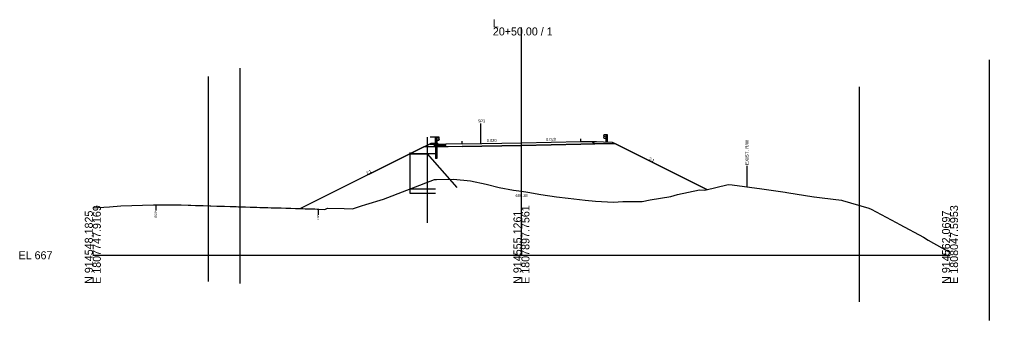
# Model space of a CAD drawing. Extents: x -26 to 1352, y -510 to 9596.
# Drawn here: x -25.7 to 313.8, y 6477.2 to 6582.4 of the extents above; entities that cross this region are included whole.
import ezdxf

# ---------------------------------------------------------------- set-up
doc = ezdxf.new("R2010")
doc.units = 0
for name, color, linetype in [('Exist Cross Section Cell', 7, 'Continuous'), ('Exist XS Center Line Elevation Label', 7, 'Continuous'), ('Exist XS Ground Line', 7, 'Continuous'), ('Old_Level_10', 7, 'Continuous'), ('Prop XS Earthwork Shape', 7, 'Continuous'), ('Prop XS EOT Tick Mark', 7, 'Continuous'), ('Prop XS Exc Vertical Line 1', 7, 'Continuous'), ('Prop XS Exc Vertical Line 2', 7, 'Continuous'), ('Prop XS Exc Vertical Line 3', 7, 'Continuous'), ('Prop XS Exc Vertical Line 4', 7, 'Continuous'), ('Prop XS Finish Grade', 7, 'Continuous'), ('Prop XS Finish Grade Earthwork', 7, 'Continuous'), ('Prop XS Finish Grade Paved Shoulder', 7, 'Continuous'), ('Prop XS Finish Grade Pavement', 7, 'Continuous'), ('Prop XS Guardrail', 7, 'Continuous'), ('Prop XS Hydro Fill Slope Data', 7, 'Continuous'), ('Prop XS Pvmt Edge Slope', 7, 'Continuous'), ('Prop XS SE Text', 7, 'Continuous'), ('Prop XS Shoulder Borrow Shape', 7, 'Continuous'), ('Prop XS Side Slope Text', 7, 'Continuous'), ('Prop XS Subgrade Earthwork', 7, 'Continuous'), ('Typical Curb CELL', 7, 'Continuous')]:
    doc.layers.add(name, color=color, linetype=linetype)

msp = doc.modelspace()

# ---------------------------------------------------------------- linework, layer by layer
at = {"layer": 'Exist Cross Section Cell'}
for p, q in [((150, 6500), (150, 6579.64)), ((0, 6500), (150, 6500)), ((150, 6500), (300, 6500))]:
    msp.add_line(p, q, dxfattribs=at)
at = {"layer": 'Exist XS Ground Line'}
msp.add_lwpolyline([(0, 6516.57), (5.8, 6516.94), (9.82, 6517.24), (21.25, 6517.63), (22.08, 6517.65), (22.94, 6517.64), (25.56, 6517.64), (25.95, 6517.65), (26.05, 6517.65), (28.2, 6517.67), (28.25, 6517.67), (30.74, 6517.59), (30.92, 6517.58), (33.39, 6517.51), (33.43, 6517.51), (33.47, 6517.51), (34.35, 6517.49), (35.89, 6517.44), (35.95, 6517.44), (36.03, 6517.44), (38.44, 6517.37), (38.66, 6517.37), (40.96, 6517.29), (41.3, 6517.28), (43.45, 6517.22), (44.36, 6517.18), (44.91, 6517.16), (45.62, 6517.14), (46.13, 6517.13), (48.12, 6517.06), (48.44, 6517.06), (50.22, 6517.01), (50.94, 6516.98), (51.75, 6516.96), (53.46, 6516.91), (55.01, 6516.86), (55.99, 6516.83), (57.41, 6516.78), (58.47, 6516.75), (59.36, 6516.72), (60.31, 6516.69), (60.65, 6516.68), (61.3, 6516.66), (62.36, 6516.63), (63.46, 6516.61), (64.57, 6516.58), (65.94, 6516.54), (67.51, 6516.5), (68.47, 6516.47), (69.34, 6516.44), (70.99, 6516.39), (72.76, 6516.34), (73.5, 6516.32), (75.41, 6516.26), (75.96, 6516.24), (76.14, 6516.24), (77.7, 6516.19), (78.53, 6516.17), (78.81, 6516.16), (79.12, 6516.15), (81.14, 6516.05), (81.41, 6516.17), (82.12, 6516.48), (87.91, 6516.35), (90.83, 6516.27), (94.06, 6517.29), (95.6, 6517.75), (101.72, 6519.63), (119.57, 6526.48), (120.33, 6526.51), (126.24, 6526.55), (132.22, 6526.01), (137.68, 6524.89), (142.24, 6523.74), (147.24, 6522.81), (150, 6522.38), (152.25, 6522.03), (156.81, 6521.29), (162.26, 6520.39), (166.38, 6519.91), (172.27, 6519.25), (175.94, 6518.93), (182.28, 6518.61), (185.51, 6518.76), (192.29, 6518.82), (195.08, 6519.34), (202.3, 6520.49), (204.65, 6521.21), (212.31, 6522.9), (214.21, 6522.8), (222.32, 6524.77), (223.78, 6524.58), (232.33, 6523.42), (233.35, 6523.29), (242.34, 6522.09), (242.92, 6521.99), (252.35, 6520.48), (252.48, 6520.46), (255.29, 6520.1), (262.05, 6519.25), (262.36, 6519.18), (271.62, 6516.41), (272.38, 6516.15), (281.19, 6511.51), (282.39, 6510.78), (290.75, 6506.28), (292.4, 6505.31), (300, 6500.91)], dxfattribs=at)
at = {"layer": 'Old_Level_10'}
for p, q in [((135.84, 6539.04), (135.84, 6546.09)), ((228.9, 6531.29), (228.9, 6523.89)), ((22.08, 6517.65), (22.08, 6515.6)), ((78.81, 6516.16), (78.81, 6514.11))]:
    msp.add_line(p, q, dxfattribs=at)
at = {"layer": 'Prop XS Earthwork Shape'}
msp.add_lwpolyline([(75.41, 6516.26), (75.96, 6516.24), (76.14, 6516.24), (77.7, 6516.19), (78.53, 6516.17), (78.81, 6516.16), (79.12, 6516.15), (81.14, 6516.05), (81.41, 6516.17), (82.12, 6516.48), (87.91, 6516.35), (90.83, 6516.27), (94.06, 6517.29), (95.6, 6517.75), (101.72, 6519.63), (119.57, 6526.48), (120.33, 6526.51), (126.24, 6526.55), (132.22, 6526.01), (137.68, 6524.89), (142.24, 6523.74), (147.24, 6522.81), (150, 6522.38), (152.25, 6522.03), (156.81, 6521.29), (162.26, 6520.39), (166.38, 6519.91), (172.27, 6519.25), (175.94, 6518.93), (182.28, 6518.61), (185.51, 6518.76), (192.29, 6518.82), (195.08, 6519.34), (202.3, 6520.49), (204.65, 6521.21), (212.31, 6522.9), (214.21, 6522.8), (214.9, 6522.96), (182.71, 6539.06), (175.65, 6538.91), (170.75, 6538.82), (150, 6538.4), (129.25, 6537.99), (124.31, 6537.89), (123.58, 6537.87), (115.8, 6537.87), (72.73, 6516.34), (74.3, 6516.29)], close=True, dxfattribs=at)
at = {"layer": 'Prop XS EOT Tick Mark'}
for p, q in [((129.25, 6538.91), (129.25, 6539.91)), ((170.75, 6539.74), (170.75, 6540.74))]:
    msp.add_line(p, q, dxfattribs=at)
at = {"layer": 'Prop XS Exc Vertical Line 1'}
msp.add_line((40.44, 6490.85), (40.44, 6562.51), dxfattribs=at)
at = {"layer": 'Prop XS Exc Vertical Line 2'}
msp.add_line((51.59, 6490.12), (51.59, 6565.36), dxfattribs=at)
at = {"layer": 'Prop XS Exc Vertical Line 3'}
msp.add_line((268.36, 6483.69), (268.36, 6558.92), dxfattribs=at)
at = {"layer": 'Prop XS Exc Vertical Line 4'}
msp.add_line((313.84, 6477.17), (313.84, 6568.37), dxfattribs=at)
at = {"layer": 'Prop XS Finish Grade'}
for p, q in [((174.75, 6539.82), (176.32, 6539.75)), ((176.32, 6539.75), (178.75, 6539.66)), ((178.75, 6539.66), (181.75, 6539.54)), ((181.75, 6539.54), (182.71, 6539.06)), ((115.8, 6537.87), (118.25, 6539.1)), ((120.56, 6539.05), (118.25, 6539.1))]:
    msp.add_line(p, q, dxfattribs=at)
at = {"layer": 'Prop XS Finish Grade Earthwork'}
for p, q in [((115.8, 6537.87), (72.73, 6516.34)), ((182.71, 6539.06), (214.9, 6522.96))]:
    msp.add_line(p, q, dxfattribs=at)
at = {"layer": 'Prop XS Finish Grade Paved Shoulder'}
for p, q in [((170.75, 6539.74), (174.75, 6539.82)), ((129.25, 6538.91), (123.58, 6538.79))]:
    msp.add_line(p, q, dxfattribs=at)
at = {"layer": 'Prop XS Finish Grade Pavement'}
for p, q in [((150, 6539.32), (170.75, 6539.74)), ((129.25, 6538.91), (150, 6539.32))]:
    msp.add_line(p, q, dxfattribs=at)
at = {"layer": 'Prop XS Guardrail'}
for p, q in [((119.93, 6541.29), (120.43, 6541.29)), ((119.93, 6538.79), (119.93, 6541.29)), ((120.43, 6541.29), (120.93, 6541.29)), ((120.43, 6541.29), (120.43, 6538.79)), ((120.93, 6540.16), (120.43, 6540.16)), ((120.93, 6541.29), (121.22, 6541.09)), ((121.22, 6540.97), (120.93, 6540.77)), ((120.93, 6540.77), (120.93, 6540.68)), ((120.93, 6540.68), (121.22, 6540.48)), ((121.22, 6540.36), (120.93, 6540.16)), ((121.22, 6541.09), (121.25, 6541.03)), ((121.25, 6541.03), (121.22, 6540.97)), ((121.22, 6540.48), (121.25, 6540.42)), ((121.25, 6540.42), (121.22, 6540.36)), ((178.78, 6541.9), (178.75, 6541.84)), ((178.75, 6541.84), (178.78, 6541.78)), ((178.78, 6541.29), (178.75, 6541.23)), ((178.75, 6541.23), (178.78, 6541.17)), ((179.07, 6542.1), (178.78, 6541.9)), ((178.78, 6541.78), (179.07, 6541.58)), ((179.07, 6541.49), (178.78, 6541.29)), ((178.78, 6541.17), (179.07, 6540.97)), ((179.57, 6542.1), (179.07, 6542.1)), ((179.07, 6541.58), (179.07, 6541.49)), ((179.07, 6540.97), (179.57, 6540.97)), ((180.07, 6542.1), (179.57, 6542.1)), ((179.57, 6542.1), (179.57, 6539.6)), ((180.07, 6539.6), (180.07, 6542.1))]:
    msp.add_line(p, q, dxfattribs=at)
at = {"layer": 'Prop XS Hydro Fill Slope Data'}
msp.add_line((118.25, 6539.1), (74.3, 6517.12), dxfattribs=at)
at = {"layer": 'Prop XS Pvmt Edge Slope'}
for p, q in [((174.75, 6539.82), (175.65, 6538.91)), ((119.56, 6538.38), (119.06, 6537.87)), ((119.56, 6538.38), (120.56, 6538.38))]:
    msp.add_line(p, q, dxfattribs=at)
at = {"layer": 'Prop XS Shoulder Borrow Shape'}
for p, q in [((117, 6541.29), (117, 6511.31)), ((121.25, 6541.29), (118.06, 6541.29)), ((119.93, 6541.29), (119.93, 6533.79)), ((120.43, 6541.29), (120.43, 6533.79)), ((118.25, 6539.1), (111, 6535.47)), ((121.25, 6538.71), (118.06, 6538.71)), ((111, 6535.97), (111, 6521.69)), ((111, 6535.47), (117, 6535.47)), ((119.93, 6535.47), (111, 6535.47)), ((112, 6535.97), (112, 6535.47)), ((117, 6535.47), (127.37, 6523.72)), ((120.43, 6533.79), (119.93, 6533.79)), ((111, 6523.19), (119.94, 6523.19)), ((111, 6521.69), (119.94, 6521.69))]:
    msp.add_line(p, q, dxfattribs=at)
at = {"layer": 'Prop XS Subgrade Earthwork'}
for p, q in [((119.05, 6537.87), (115.8, 6537.87)), ((123.58, 6537.87), (119.05, 6537.87)), ((124.31, 6537.89), (123.58, 6537.87)), ((129.25, 6537.99), (124.31, 6537.89)), ((129.25, 6537.99), (150, 6538.4)), ((150, 6538.4), (170.75, 6538.82)), ((170.75, 6538.82), (175.65, 6538.91)), ((175.65, 6538.91), (182.71, 6539.06))]:
    msp.add_line(p, q, dxfattribs=at)
at = {"layer": 'Typical Curb CELL'}
for p, q in [((120.56, 6538.38), (120.56, 6539.05)), ((121.25, 6538.71), (120.56, 6539.05)), ((120.56, 6538.38), (123.58, 6538.38)), ((120.6, 6538.67), (120.75, 6538.72)), ((120.74, 6538.63), (120.6, 6538.67)), ((120.75, 6538.72), (120.74, 6538.63)), ((121.27, 6538.59), (121.17, 6538.52)), ((121.17, 6538.52), (121.33, 6538.48)), ((123.57, 6538.79), (121.25, 6538.71)), ((121.33, 6538.48), (121.27, 6538.59)), ((122.01, 6538.65), (121.98, 6538.53)), ((121.98, 6538.53), (122.1, 6538.53)), ((122.1, 6538.53), (122.01, 6538.65)), ((122.52, 6538.59), (122.41, 6538.52)), ((122.41, 6538.52), (122.58, 6538.48)), ((122.58, 6538.48), (122.52, 6538.59)), ((123.26, 6538.65), (123.22, 6538.53)), ((123.22, 6538.53), (123.35, 6538.53)), ((123.35, 6538.53), (123.26, 6538.65)), ((123.58, 6538.79), (123.58, 6538.79)), ((123.58, 6538.38), (123.58, 6538.78))]:
    msp.add_line(p, q, dxfattribs=at)
for centre in [(120.63, 6538.76), (120.72, 6538.49), (120.84, 6538.54), (121.1, 6538.57), (121.12, 6538.51), (121.3, 6538.43), (121.32, 6538.53), (121.52, 6538.49), (121.56, 6538.61), (121.69, 6538.58), (121.72, 6538.45), (121.78, 6538.49), (121.97, 6538.49), (122.09, 6538.54), (122.19, 6538.53), (122.28, 6538.48), (122.34, 6538.62), (122.35, 6538.57), (122.37, 6538.51), (122.57, 6538.53), (122.77, 6538.49), (122.81, 6538.61), (122.86, 6538.58), (122.94, 6538.58), (122.97, 6538.45), (123.03, 6538.49), (123.09, 6538.66), (123.46, 6538.74), (123.49, 6538.61)]:
    msp.add_circle(centre, 0.00802, dxfattribs=at)
msp.add_arc((123.57, 6538.78), 0.0104, 0, 92.048, dxfattribs=at)

# ---------------------------------------------------------------- texts
at = {"layer": 'Exist Cross Section Cell'}
for s, p in [('L', (140, 6579.64)), ('20+50.00 / 1', (140, 6576.84)), ('EL 667', (-26, 6498.6))]:
    msp.add_text(s, height=2.8, dxfattribs=at).set_placement(p)
for s, p in [('E 1807747.9169', (2.8, 6490)), ('E 1807897.7561', (152.8, 6490)), ('E 1808047.5953', (302.8, 6490)), ('N 914548.1825', (0, 6490)), ('N 914555.1261', (150, 6490)), ('N 914562.0697', (300, 6490))]:
    msp.add_text(s, height=2.8, rotation=90, dxfattribs=at).set_placement(p)
at = {"layer": 'Exist XS Center Line Elevation Label'}
msp.add_text('689.38', height=1, dxfattribs=at).set_placement((147.95, 6520.38))
at = {"layer": 'Old_Level_10'}
msp.add_text('SP3', height=1, dxfattribs=at).set_placement((134.73, 6546.41))
for s, height, p in [('EXIST. R/W', 1.181, (229.49, 6531.59)), ('EOP', 0.787, (22.47, 6513.2)), ('EOP', 0.787, (79.2, 6511.72))]:
    msp.add_text(s, height=height, rotation=90, dxfattribs=at).set_placement(p)
at = {"layer": 'Prop XS SE Text'}
for p in [(137.88, 6539.58), (158.63, 6539.99)]:
    msp.add_text('0.020', height=1, rotation=1.1458, dxfattribs=at).set_placement(p)
at = {"layer": 'Prop XS Side Slope Text'}
for rotation, p in [(333.4349, (194.51, 6533.42)), (26.5651, (95.93, 6528.19))]:
    msp.add_text('2:1', height=1, rotation=rotation, dxfattribs=at).set_placement(p)

doc.saveas('drawing.dxf')
